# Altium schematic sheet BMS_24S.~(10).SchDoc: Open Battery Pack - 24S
size A4; Author: Morgane Vallée; Revision: 1.0; SheetNumber: 3; SheetTotal: 5
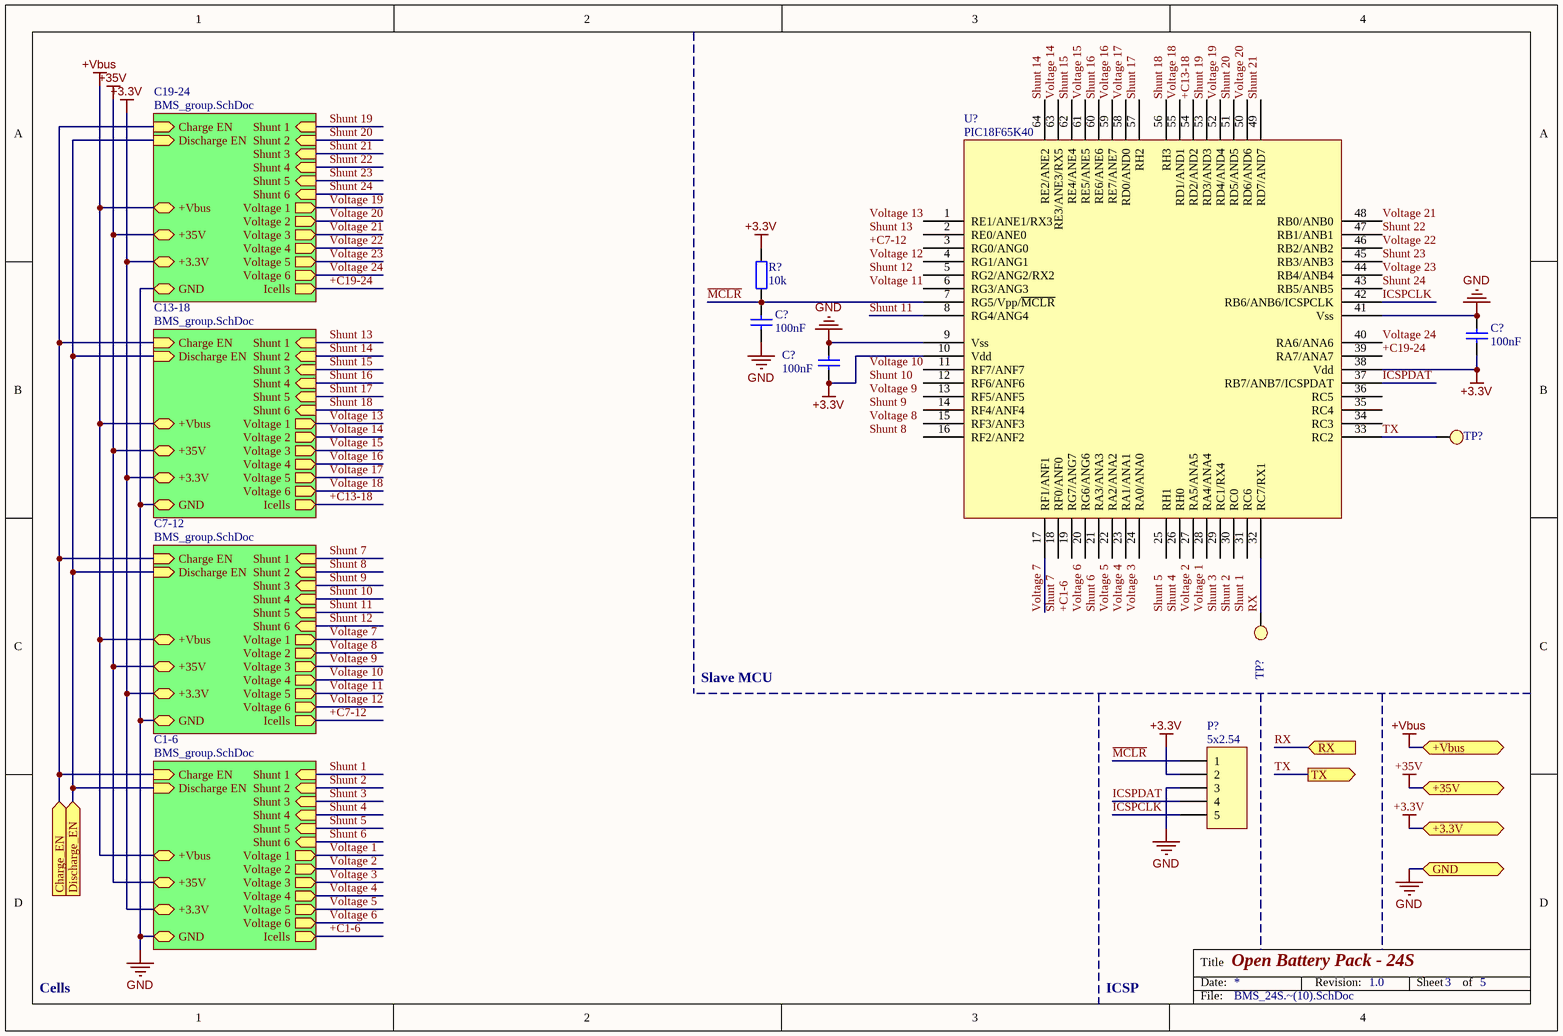
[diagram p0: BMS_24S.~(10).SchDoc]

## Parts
(Parts that share a designator on the sheet are numbered #1, #2 ... from top to bottom, then left to right.)
C?#1  100nF  [C0603]
C?#2  100nF  [C0603]
C?#3  100nF  [C0603]
P?  5x2.54  [HDR1X5]
R?  10k  [R0603]
TP?#1  Test Point  [Test Point]  (value not drawn)
TP?#2  Test Point  [Test Point]  (value not drawn)
U?  PIC18F65K40  [LQFP64]

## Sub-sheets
C1-6 = BMS_group.SchDoc: +Vbus, Shunt 1 (in), Shunt 2 (in), Shunt 3 (in), Shunt 4 (in), Shunt 5 (in), Shunt 6 (in), Voltage 1 (out), Voltage 2 (out), Voltage 3 (out), Voltage 4 (out), +3.3V, Voltage 5 (out), Voltage 6 (out), Charge EN (in), Discharge EN (in), Icells (out), GND, +35V
C7-12 = BMS_group.SchDoc: +Vbus, Shunt 1 (in), Shunt 2 (in), Shunt 3 (in), Shunt 4 (in), Shunt 5 (in), Shunt 6 (in), Voltage 1 (out), Voltage 2 (out), Voltage 3 (out), Voltage 4 (out), +3.3V, Voltage 5 (out), Voltage 6 (out), Charge EN (in), Discharge EN (in), Icells (out), GND, +35V
C13-18 = BMS_group.SchDoc: +Vbus, Shunt 1 (in), Shunt 2 (in), Shunt 3 (in), Shunt 4 (in), Shunt 5 (in), Shunt 6 (in), Voltage 1 (out), Voltage 2 (out), Voltage 3 (out), Voltage 4 (out), +3.3V, Voltage 5 (out), Voltage 6 (out), Charge EN (in), Discharge EN (in), Icells (out), GND, +35V
C19-24 = BMS_group.SchDoc: +Vbus, Shunt 1 (in), Shunt 2 (in), Shunt 3 (in), Shunt 4 (in), Shunt 5 (in), Shunt 6 (in), Voltage 1 (out), Voltage 2 (out), Voltage 3 (out), Voltage 4 (out), +3.3V, Voltage 5 (out), Voltage 6 (out), Charge EN (in), Discharge EN (in), Icells (out), GND, +35V

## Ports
+3.3V, +35V, +Vbus, Charge_EN (in), Discharge_EN (in), GND, RX (in), TX (out)

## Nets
+3.3V: C?#2.2 C?#3.2 P?.2 R?.2 U?.10(Vdd) U?.38(Vdd) ; port +3.3V, sheet C1-6/+3.3V, sheet C7-12/+3.3V, sheet C13-18/+3.3V, sheet C19-24/+3.3V
+35V: port +35V, sheet C1-6/+35V, sheet C7-12/+35V, sheet C13-18/+35V, sheet C19-24/+35V
+Vbus: port +Vbus, sheet C1-6/+Vbus, sheet C7-12/+Vbus, sheet C13-18/+Vbus, sheet C19-24/+Vbus
GND: C?#1.1 C?#2.1 C?#3.1 P?.3 U?.9(Vss) U?.41(Vss) ; port GND, sheet C1-6/GND, sheet C7-12/GND, sheet C13-18/GND, sheet C19-24/GND
+C13-18: U?.54(RD2/AND2) ; sheet C13-18/Icells
+C19-24: U?.39(RA7/ANA7) ; sheet C19-24/Icells
Charge_EN: port Charge_EN, sheet C1-6/Charge EN, sheet C7-12/Charge EN, sheet C13-18/Charge EN, sheet C19-24/Charge EN
Discharge_EN: port Discharge_EN, sheet C1-6/Discharge EN, sheet C7-12/Discharge EN, sheet C13-18/Discharge EN, sheet C19-24/Discharge EN
ICSPCLK: P?.5 U?.42(RB6/ANB6/ICSPCLK)
ICSPDAT: P?.4 U?.37(RB7/ANB7/ICSPDAT)
~{MCLR}: C?#1.2 P?.1 R?.1 U?.7(RG5/Vpp/~{MCLR})
RX: TP?#2.1 U?.32(RC7/RX1) ; port RX
Shunt 11: U?.8(RG4/ANG4) ; sheet C7-12/Shunt 5
Shunt 14: U?.64(RE2/ANE2) ; sheet C13-18/Shunt 2
Shunt 15: U?.62(RE4/ANE4) ; sheet C13-18/Shunt 3
Shunt 16: U?.60(RE6/ANE6) ; sheet C13-18/Shunt 4
Shunt 17: U?.57(RH2) ; sheet C13-18/Shunt 5
Shunt 18: U?.56(RH3) ; sheet C13-18/Shunt 6
Shunt 19: U?.53(RD3/AND3) ; sheet C19-24/Shunt 1
Shunt 20: U?.51(RD5/AND5) ; sheet C19-24/Shunt 2
Shunt 21: U?.49(RD7/AND7) ; sheet C19-24/Shunt 3
Shunt 22: U?.47(RB1/ANB1) ; sheet C19-24/Shunt 4
Shunt 23: U?.45(RB3/ANB3) ; sheet C19-24/Shunt 5
Shunt 24: U?.43(RB5/ANB5) ; sheet C19-24/Shunt 6
TX: TP?#1.1 U?.33(RC2) ; port TX
Voltage 7: U?.17(RF1/ANF1) ; sheet C7-12/Voltage 1
Voltage 14: U?.63(RE3/ANE3/RX5) ; sheet C13-18/Voltage 2
Voltage 15: U?.61(RE5/ANE5) ; sheet C13-18/Voltage 3
Voltage 16: U?.59(RE7/ANE7) ; sheet C13-18/Voltage 4
Voltage 17: U?.58(RD0/AND0) ; sheet C13-18/Voltage 5
Voltage 18: U?.55(RD1/AND1) ; sheet C13-18/Voltage 6
Voltage 19: U?.52(RD4/AND4) ; sheet C19-24/Voltage 1
Voltage 20: U?.50(RD6/AND6) ; sheet C19-24/Voltage 2
Voltage 21: U?.48(RB0/ANB0) ; sheet C19-24/Voltage 3
Voltage 22: U?.46(RB2/ANB2) ; sheet C19-24/Voltage 4
Voltage 23: U?.44(RB4/ANB4) ; sheet C19-24/Voltage 5
Voltage 24: U?.40(RA6/ANA6) ; sheet C19-24/Voltage 6

Not connected (* = marked no-connect by the designer): U? 1(RE1/ANE1/RX3) 2(RE0/ANE0) 3(RG0/ANG0) 4(RG1/ANG1) 5(RG2/ANG2/RX2) 6(RG3/ANG3) 11(RF7/ANF7) 12(RF6/ANF6) 13(RF5/ANF5) 14(RF4/ANF4) 15(RF3/ANF3) 16(RF2/ANF2) 18(RF0/ANF0) 19(RG7/ANG7) 20(RG6/ANG6) 21(RA3/ANA3) 22(RA2/ANA2) 23(RA1/ANA1) 24(RA0/ANA0) 25(RH1) 26(RH0) 27(RA5/ANA5) 28(RA4/ANA4) 29(RC1/RX4) 30(RC0) 31(RC6) 34(RC3) 35(RC4) 36(RC5)

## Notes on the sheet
- Slave MCU
- Cells
- ICSP
- Labels drawn without touching a wire or pin: +C1-6, +C7-12, Shunt 1, Shunt 2, Shunt 3, Shunt 4, Shunt 5, Shunt 6, Shunt 7, Shunt 8, Shunt 9, Shunt 10, Shunt 12, Shunt 13, Voltage 1, Voltage 2, Voltage 3, Voltage 4, Voltage 5, Voltage 6, Voltage 8, Voltage 9, Voltage 10, Voltage 11, Voltage 12, Voltage 13

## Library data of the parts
C?#1-C?#3 = Cap: Capacitor
P? = Header 5: Header, 5-Pin
R? = Res2: Resistor
U? = PIC18F65K40: 64-Pin, Low-Power, High-Performance Microcontrollers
